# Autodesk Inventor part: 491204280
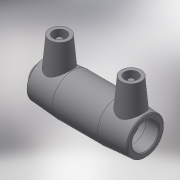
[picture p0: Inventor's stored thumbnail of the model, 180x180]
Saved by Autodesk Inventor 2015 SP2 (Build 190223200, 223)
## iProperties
Created: 2017-06
Part Number: 491204280
Material: Generic
Description: PLASSON END CAP 280
Document SubType Name: Modeling
Designer: KIM
Mass: 38.9236 g
Surface Area: 152.394 cm^2
Volume: 38.9236 cm^3
Density: 1 g/cm^3
Appearance: Default
Author: KIM
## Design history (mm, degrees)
derived "491204.ipt"
feature "Solid1::491204.ipt"
tag "TaggingFeature1"
body "Solid1"
other parameters: "d0" = 275, "d3" = 134, "d4" = 99, "d5" = 306, "d6" = 266, "d8" = 168 deg, "d10" = 53.6, "d11" = 17.86667, "d13" = 316.8, "d14" = 17.6296, "d15" = 134, "d16" = 134, "d17" = 266, "d19" = 3.52592, "d20" = 168 deg, "d22" = 319.6, "d24" = 310.012, "d25" = 135 deg, "d26" = 142.56, "d27" = 135 deg, "d30" = 15, "d31" = 126.72, "d34" = 5 deg, "d35" = 15, "d39" = 5 deg, "d41" = 4, "d42" = 14, "d43" = 0, "d45" = 4, "d46" = 14, "d47" = 0, "d48" = 396, "d49" = 1, "d51" = 224, "d52" = 7.128, "d53" = 308, "d54" = 7.128, "d56" = 28, "d57" = 8.4, "d60" = 59.4, "d61" = 5.6, "d63" = 396, "d64" = 1, "d66" = 224, "d67" = 56, "d68" = 308, "d69" = 7.92, "d70" = 0, "d71" = 7.128, "d72" = 3, "d73" = 0, "d74" = 38.86, "d75" = 12.95333, "d76" = 3, "d77" = 0, "L_" = 396, "L_1" = 134, "d_2" = 12, "L_0" = 275, "d55" = 28
